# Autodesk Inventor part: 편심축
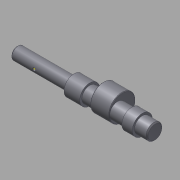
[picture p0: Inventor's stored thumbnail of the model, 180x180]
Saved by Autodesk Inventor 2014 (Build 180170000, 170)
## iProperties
Company: 한국ATC센터
Created: 2015-12
Part Number: 편심축
Document SubType Name: Modeling
Designer: mdu
Density: 7.86 g/cm^3
Mass: 218.612 g
Surface Area: 79.4502 cm^2
Volume: 27.8133 cm^3
Material: 강철, 연강
Appearance: 강철
Author: mdu
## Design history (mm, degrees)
sketch "스케치1"
  geometry: L1 (-84.5, 0)-(84.5, 0); L2 (-84.5, 0)-(-84.5, 6); L3 (-84.5, 6)-(-30.5, 6); L4 (-30.5, 6)-(-30.5, 9.5); L5 (-30.5, 9.5)-(-15.5, 9.5); L6 (-15.5, 9.5)-(-15.5, 7.5); L7 (-15.5, 7.5)-(46.5, 7.5); L8 (84.5, 6)-(84.5, 0); L9 (34.5, 7.5)-(34.5, 9.5); L10 (34.5, 9.5)-(24.5, 9.5); L11 (24.5, 9.5)-(24.5, 7.5); L12 (46.5, 7.5)-(46.5, 6); L13 (46.5, 6)-(84.5, 6); 2 further points
  constraints: 26 end point, 6 parallel, 6 perpendicular, 2 point on line, 1 coincident, 1 horizontal, 1 midpoint
  dimensions: "d1" = 12 diameter of L3 L1; "d2" = 15 diameter of L7 L1; "d4" = 15 distance of L4.end L5.end; "d5" = 19 diameter of L5 L1; "d24" = 10 distance of L9.end L10.end; "d25" = 19 diameter of L10 L1; "d27" = 40 distance between parallel lines of L11 L6; "d28" = 54 distance of L2.end L3.end; "d29" = 50 distance between parallel lines of L8 L9; "d41" = 38 distance between parallel lines of L8 L12; "d42" = 12 diameter of L13 L1
revolve "회전1" stored, may be unused: angle "d6" = 90 deg
node "작업 평면1"
sketch "스케치2"
  geometry: C1 r 7.5 at (0, 0) reference; C2 r 12.5 at (0, 4.5); 1 further point
  constraints: 1 centre point, 1 vertical alignment
  dimensions: "d8" = 4.5 distance of point (0, 0) C2.centre; "d9" = 25 diameter of C2
extrude "돌출1" join sketch "스케치2" distance "d10" = 18; taper "d11" = 0 deg
chamfer "모따기1" distance "d12" = 1; stored, may be unused: second distance "d13" = 2, angle "d14" = 45 deg
chamfer "모따기2" distance "d15" = 0.5; stored, may be unused: second distance "d16" = 2, angle "d17" = 45 deg
node "작업 평면2"
sketch "스케치3"
  geometry: L1 (4, -2)-(18, -2); L2 (18, 2)-(4, 2); L3 (27, 5)-(27, -5) reference; A1 r 2 centre (18, 0) between (18, -2) and (18, 2); A2 r 2 centre (4, 0) between (4, 2) and (4, -2); 2 further points
  constraints: 4 end point, 4 point on circle, 4 tangent, 2 centre point, 1 horizontal, 1 horizontal alignment, 1 midpoint, 1 parallel
  dimensions: "d18" = 7 distance edge to line of A1 L3; "d19" = 4 distance between parallel lines of L2 L1; "d20" = 18 dimension on A1 A2
extrude "돌출2" cut sketch "스케치3" distance "d21" = 2.5; taper "d22" = 0 deg
revolve "회전2" stored, may be unused: angle "d26" = 90 deg
node "작업 평면3"
sketch "스케치4"
  geometry: L1 (44, 5)-(44, -5) reference; 2 further points
  constraints: 1 horizontal alignment
  dimensions: "d30" = 12 distance from line of point (32, 0) L1
hole "구멍1" sketch "스케치4" at (32, 0) diameter "d31" = 6; stored, may be unused: countersink angle "d35" = 90 deg, drill point angle "d37" = 118 deg; dims "d32" = 6, "d33" = 14, "d34" = 3, "d36" = 8
node "작업 평면4"
sketch "스케치5"
  geometry: C1 r 3 at (32, 0) reference; C2 r 8 at (32, 0); 2 further points
  constraints: 1 centre point, 1 coincident, 1 other
  dimensions: "d38" = 16 diameter of C2
extrude "돌출3" cut sketch "스케치5" distance "d39" = 3; taper "d40" = 0 deg
sketch "스케치6"
  geometry: L1 (-83.5, -6)-(-30.5, -6) reference; L2 (-84.5, -5)-(-84.5, 5) reference; L3 (-83.5, 6)-(-30.5, 6) reference; L4 (-62.5, 6)-(-62.5, -6); L5 (-62.5, -6)-(-61, -6); L6 (-62.5, -4.5)-(-61, -6); L7 (-62.5, -6)-(-62.5, -4.5); 2 further points
  constraints: 8 end point, 4 point on line, 2 perpendicular, 1 coincident
  dimensions: "d43" = 22 distance between parallel lines of L4 L2; "d44" = 45 deg angle of L6 L7; "d45" = 3 diameter of L5.end L4
revolve "회전3" stored, may be unused: angle "d46" = 90 deg
node "작업점1"
chamfer "모따기3" distance "d47" = 0.5; stored, may be unused: second distance "d48" = 2, angle "d49" = 45 deg
sketch "스케치7"
  geometry: C1 r 7.5 at (0, 0) reference; 1 further point
extrude "돌출4" cut sketch "스케치7" stored distance "d50" = 10; taper "d51" = 0 deg
chamfer "모따기4" distance "d52" = 1; stored, may be unused: second distance "d53" = 2, angle "d54" = 45 deg
node "작업 평면5"
node "솔리드1"
node "투영된 루프1"
other parameters: "d7" = 8.5
